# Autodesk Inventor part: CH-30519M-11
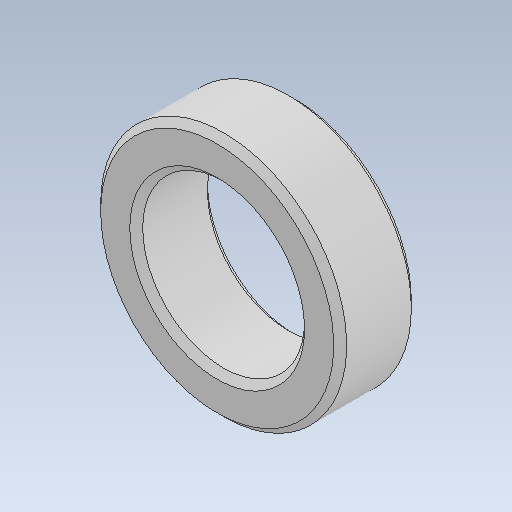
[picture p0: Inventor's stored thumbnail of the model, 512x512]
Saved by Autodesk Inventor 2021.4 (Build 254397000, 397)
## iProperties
Created: 2017-11
Part Number: CH-30519M-11
Material: Ogólny
Document SubType Name: Modeling
Designer: user
Density: 1 g/cm^3
Appearance: Domyślna
Author: user
Revision Number: ÈÎºÎ
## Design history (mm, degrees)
feature "µ¹½Ç1"
node "Bryła1"
